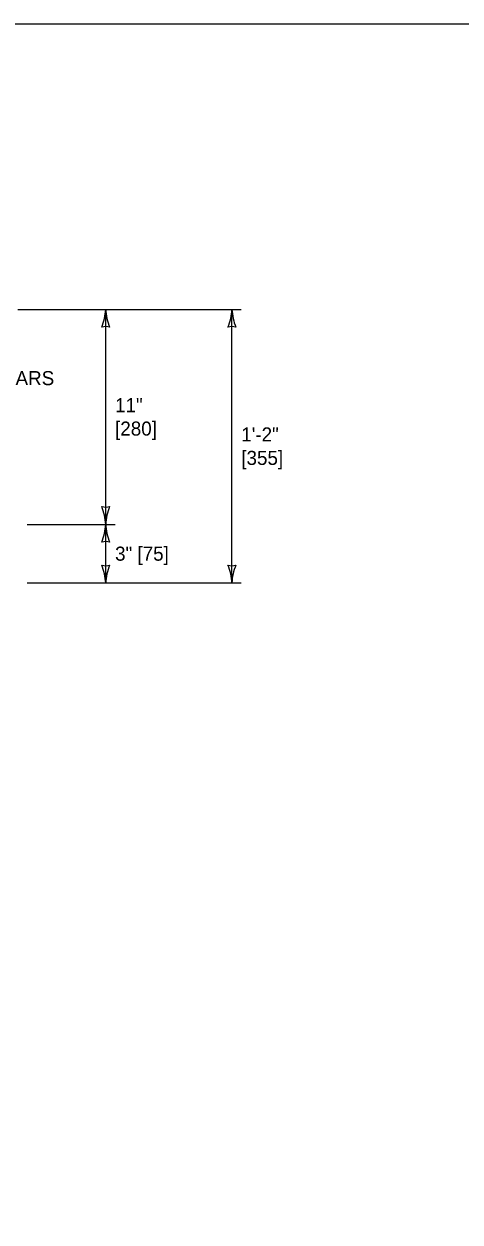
# Model space of a CAD drawing. Extents: x 49991.4 to 50021, y 49987.6 to 50011.4.
# Drawn here: x 50009.61 to 50011.47, y 49993.89 to 49999 of the extents above; entities that cross this region are included whole.
import ezdxf

# ---------------------------------------------------------------- set-up
doc = ezdxf.new("R2010")
doc.units = 0
for name, color, linetype in [('Level 1', 7, 'Continuous'), ('Level 2', 7, 'Continuous'), ('Level 3', 7, 'Continuous')]:
    doc.layers.add(name, color=color, linetype=linetype)

msp = doc.modelspace()

# ---------------------------------------------------------------- linework, layer by layer
at = {"layer": 'Level 1'}
msp.add_lwpolyline([(49999.3835, 49998.9992), (50016.7501, 49998.9992), (50016.7501, 49987.7988), (49999.3835, 49987.7988)], close=True, dxfattribs=at)
at = {"layer": 'Level 3'}
for p, q in [((50009.5838, 49997.7819), (50010.5366, 49997.7819)), ((50009.9585, 49996.8649), (50009.9585, 49997.7819)), ((50010.4966, 49996.6149), (50010.4966, 49997.7819)), ((50009.6238, 49996.8649), (50009.9985, 49996.8649)), ((50009.9585, 49996.6149), (50009.9585, 49996.8649)), ((50009.6238, 49996.6149), (50010.5366, 49996.6149))]:
    msp.add_line(p, q, dxfattribs=at)
for centre, radius, start, end in [((50009.7364, 49997.791), 0.2223, 337.456, 357.6395), ((50010.1912, 49997.7934), 0.233, 182.8273, 202.0772), ((50010.2745, 49997.791), 0.2223, 337.456, 357.6395), ((50010.7294, 49997.7934), 0.233, 182.8273, 202.0772), ((50009.9585, 49997.6537), 0.0548, 72.1388, 107.8612), ((50010.4966, 49997.6537), 0.0548, 72.1388, 107.8612), ((50009.9585, 49996.9931), 0.0548, 252.1388, 287.8612), ((50009.7258, 49996.8534), 0.233, 2.8273, 22.0772), ((50010.1806, 49996.8557), 0.2223, 157.456, 177.6395), ((50009.7364, 49996.874), 0.2223, 337.456, 357.6395), ((50010.1912, 49996.8764), 0.233, 182.8273, 202.0772), ((50009.9585, 49996.7367), 0.0548, 72.1388, 107.8612), ((50009.9585, 49996.7431), 0.0548, 252.1388, 287.8612), ((50009.7258, 49996.6034), 0.233, 2.8273, 22.0772), ((50010.1806, 49996.6057), 0.2223, 157.456, 177.6395), ((50010.4966, 49996.7431), 0.0548, 252.1388, 287.8612), ((50010.2639, 49996.6034), 0.233, 2.8273, 22.0772), ((50010.7188, 49996.6057), 0.2223, 157.456, 177.6395)]:
    msp.add_arc(centre, radius, start, end, dxfattribs=at)

# ---------------------------------------------------------------- texts
at = {"layer": 'Level 2'}
for s, p in [('[#13] BARS', (50009.3199, 49997.4586)), ('11"', (50009.9985, 49997.3434)), ('[280]', (50009.9985, 49997.2434)), ('1\'-2"', (50010.5366, 49997.2184)), ('[355]', (50010.5366, 49997.1184)), ('3" [75]', (50009.9985, 49996.7099))]:
    msp.add_text(s, height=0.06, dxfattribs=at).set_placement(p)

doc.saveas('drawing.dxf')
